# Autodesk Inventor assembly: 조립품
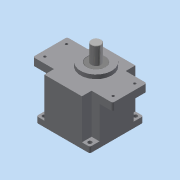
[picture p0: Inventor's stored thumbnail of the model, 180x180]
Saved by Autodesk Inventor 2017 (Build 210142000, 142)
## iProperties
Part Number: 조립품
Material: 일반
Document SubType Name: Assembly
Designer: user
Author: user
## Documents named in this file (10)
- C:\Users\user\Desktop\700116V1006\조립품.iam
- C:\Users\user\Desktop\700116V1006\메인 축.ipt
- C:\Users\user\Desktop\700116V1006\베어링 608.ipt
- C:\Users\user\Desktop\700116V1006\베어링 6003.ipt
- C:\Users\user\Desktop\700116V1006\본체.ipt
- C:\Users\user\Desktop\700116V1006\볼트 M4.ipt
- C:\Users\user\Desktop\700116V1006\서브 축.ipt
- C:\Users\user\Desktop\700116V1006\오일 실 8 22 7.ipt
- C:\Users\user\Desktop\700116V1006\오일 실 17 32 8.ipt
- C:\Users\user\Desktop\700116V1006\커버.ipt
